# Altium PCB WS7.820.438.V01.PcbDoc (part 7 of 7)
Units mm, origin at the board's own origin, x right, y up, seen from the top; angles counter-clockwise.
Board outline 143.01 x 224 mm, 4 copper layers (Top Layer, G2, S3, Bottom Layer); 863 components, 638 nets, 2623 pads, 4664 vias.
Unrouted connection lines stored in the file: 16.
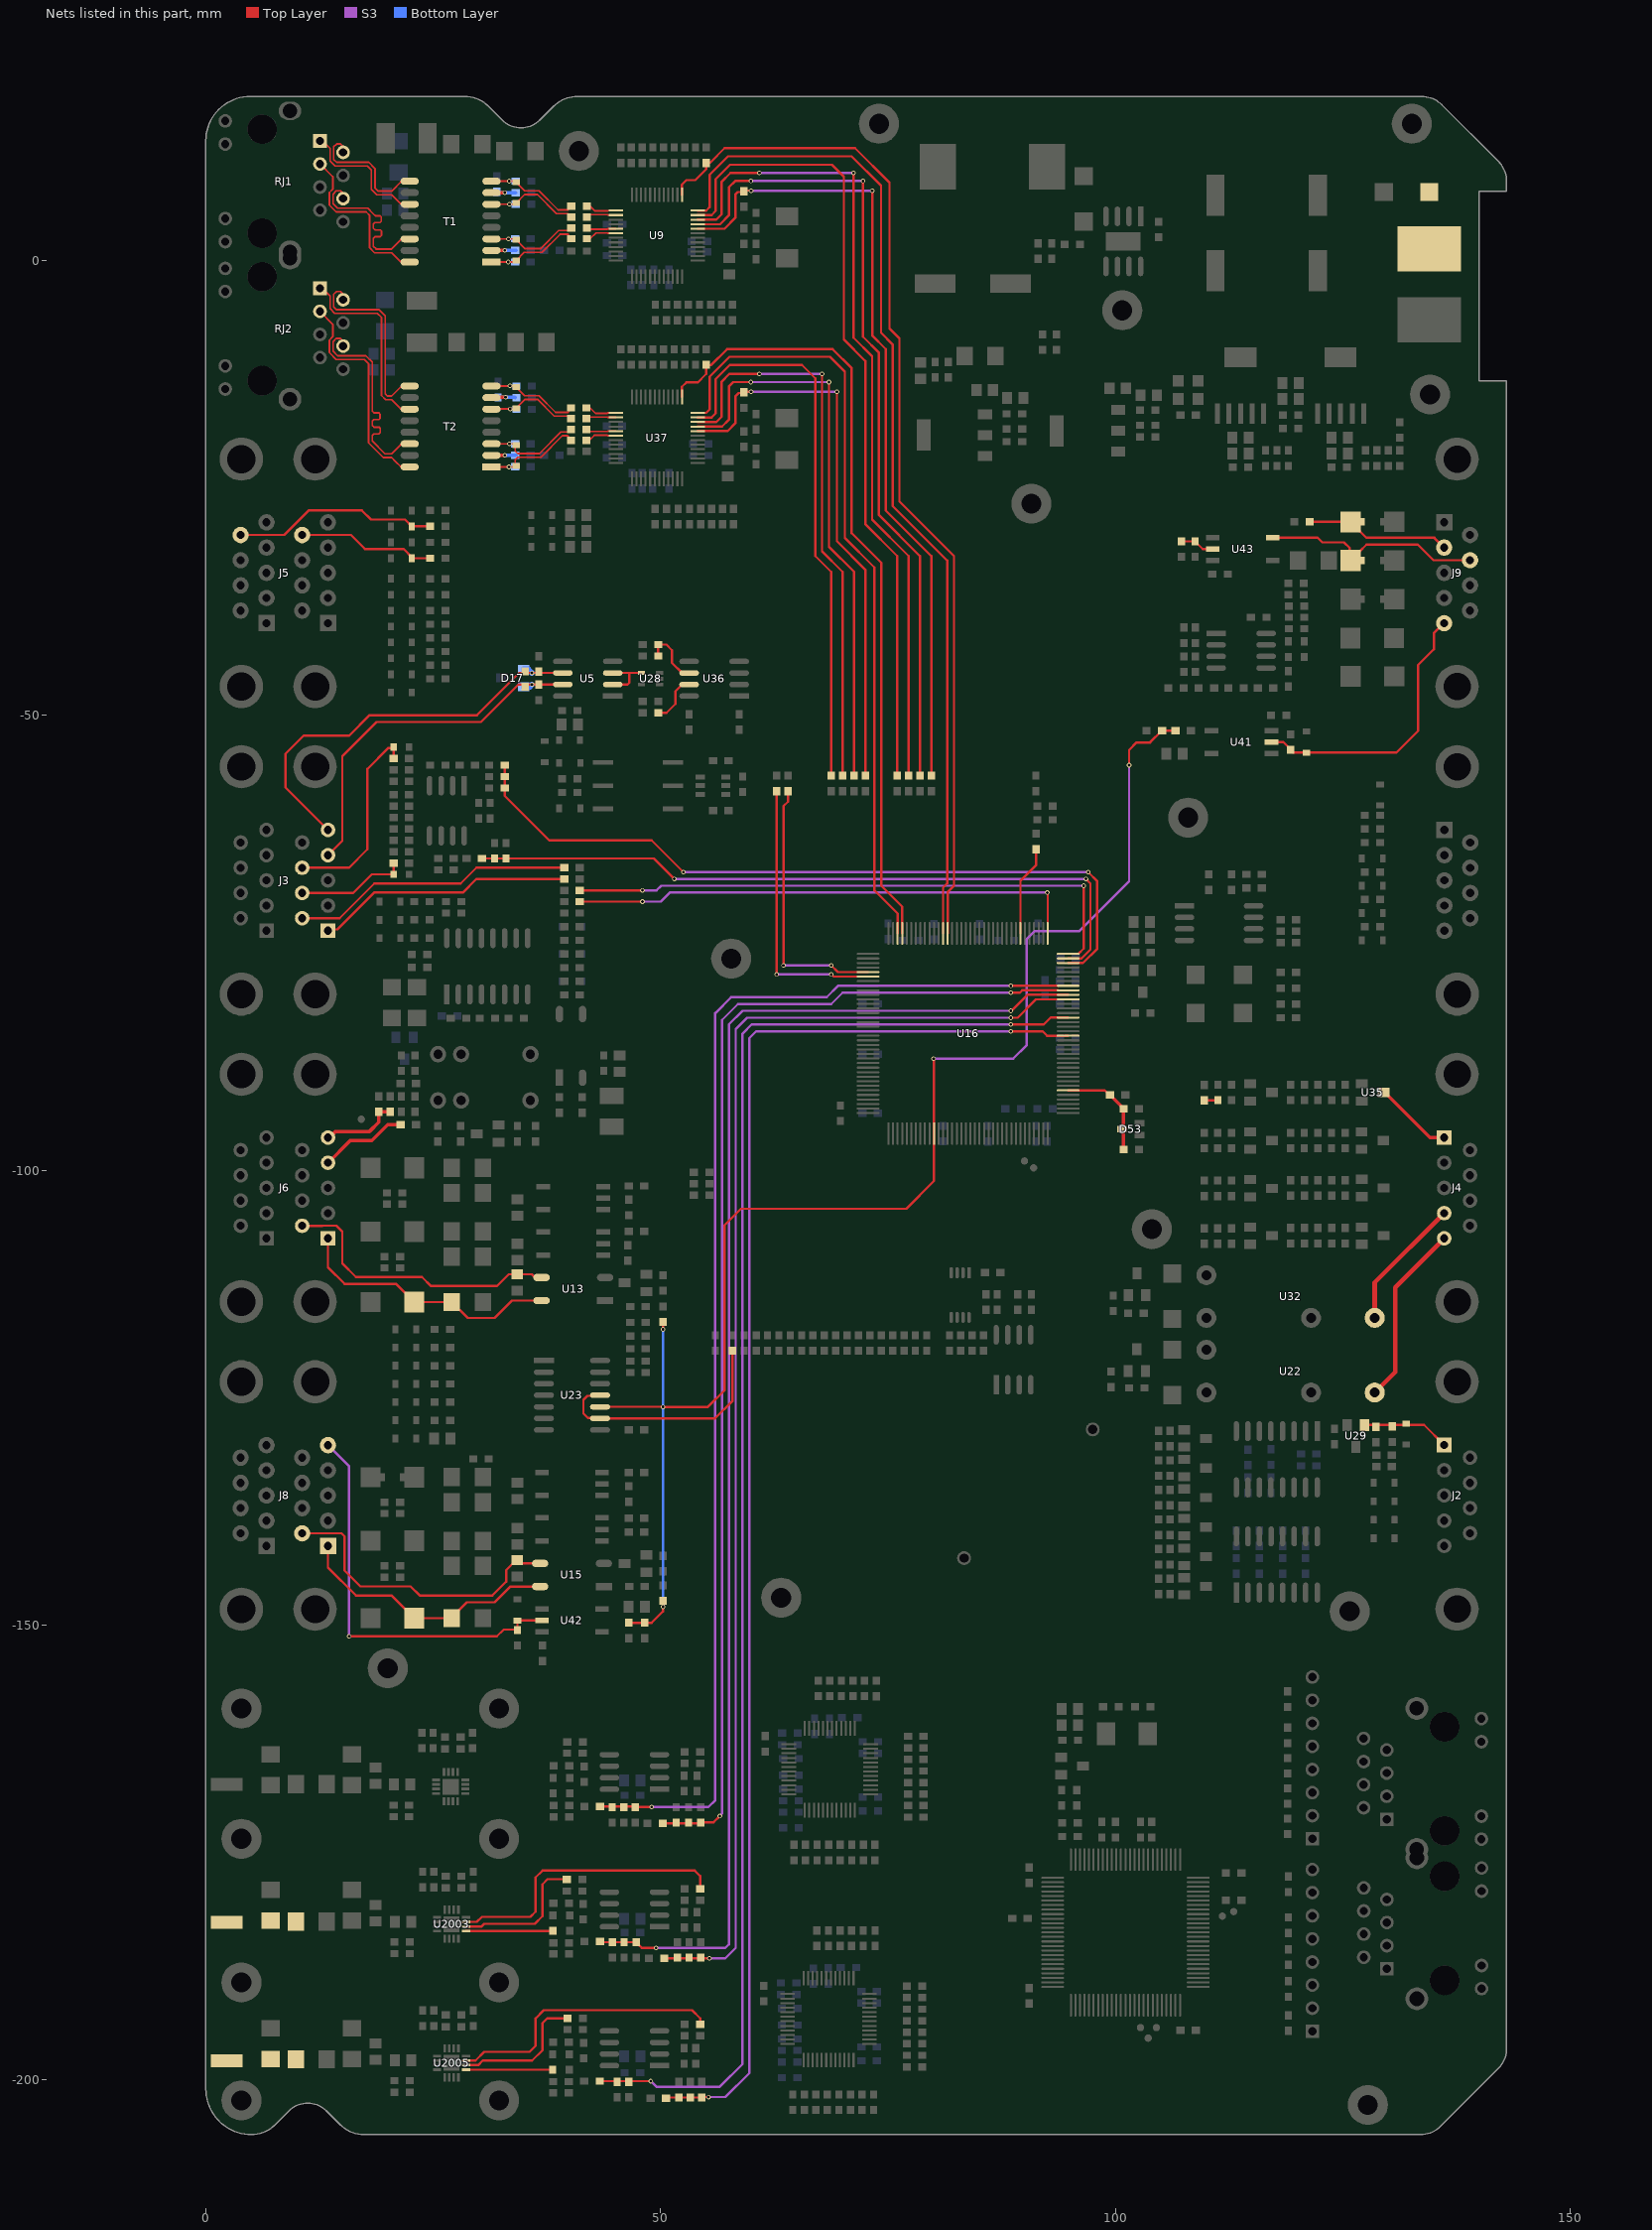
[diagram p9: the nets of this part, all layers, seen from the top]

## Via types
v1: diameter 0.508, hole 0.305, Top Layer to Bottom Layer, tented both sides, 4404 vias
v2: diameter 0.508, hole 0.3, Top Layer to Bottom Layer, tented both sides, 200 vias
v3: diameter 0.813, hole 0.508, Top Layer to Bottom Layer, tented both sides, 31 vias
v4: diameter 0.457, hole 0.305, Top Layer to Bottom Layer, tented both sides, 10 vias
v5: diameter 0.66, hole 0.406, Top Layer to Bottom Layer, tented both sides, 9 vias
v6: diameter 0.762, hole 0.406, Top Layer to Bottom Layer, tented both sides, 6 vias
v7: diameter 0.711, hole 0.406, Top Layer to Bottom Layer, tented both sides, 4 vias

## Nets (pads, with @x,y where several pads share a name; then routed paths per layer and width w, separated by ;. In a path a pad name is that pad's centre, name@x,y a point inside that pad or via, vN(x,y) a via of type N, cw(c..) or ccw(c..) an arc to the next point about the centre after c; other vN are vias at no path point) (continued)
PWM_Ext_IN: D65.1 D70.2 J9.7 U43.3 | length 24.9
  Top Layer w0.254: U43.3@117.3,-30.48 122.23,-30.48 122.75,-31 125.131,-31 125.749,-31.618 125.749,-32.899 D70.2@125.85,-33 ; D70.2@125.85,-32.95 126.823,-31.977 126.873,-31.977 127.6,-31.25 133.25,-31.25 134.966,-32.966 J9.7@138.979,-32.966
PWM_Ext_IN_ISO: R302.1 R317.2 U43.5 | length 3.9
  Top Layer w0.254: R302.1@107.25,-30.9 R317.2@108.75,-30.9 ; R317.2@108.692,-30.842 R317.2@108.75,-30.9 ; U43.5@110.7,-31.75 110.694,-31.744 109.594,-31.744 108.946,-31.096 108.896,-31.096 108.75,-30.95 R317.2@108.75,-30.9
PWM_Int: D34.2 D69.1 J9.2 R90.1 | length 16
  Top Layer w0.254: R90.1@121.35,-28.75 D34.2@125.85,-28.75 125.85,-28.8 126.823,-29.773 126.873,-29.773 127.6,-30.5 135.058,-30.5 J9.2@136.139,-31.581
RC2+_PSW: J6.B4 R224.1 | length 9.7
  Top Layer w0.381: J6.B4@13.426,-99.193 15.869,-96.75 18.25,-96.75 20,-95 R224.1@21.4,-95
RC2-_PSW: J6.B5 R313.1 R314.1 | length 8.5
  Top Layer w0.381: J6.B5@13.5,-96.25 13.759,-96.25 14.259,-95.75 18,-95.75 19,-94.75 R313.1@19,-93.6 R314.1@20.25,-93.6
red_24V: J4.1 U35.3 | length 8.7
  Top Layer w0.381: U35.3@129.47,-91.46 129.62,-91.46 134.583,-96.423 J4.1@136.139,-96.423
red_ctrl: R208.2 R299.1 | length 1.5
  Top Layer w0.254: R208.2@109.75,-92.35 111.23,-92.35 R299.1@111.27,-92.31
reset: C93.2 D27.1 J2.1 R153.1 U29.1 | length 9.7
  Top Layer w0.254: U29.1@127.376,-128.016 133.932,-128.016 J2.1@136.139,-130.223
RF_EN1: D54.1 J8.B5 R58.2 U42.5 | length 44.4
  Top Layer w0.254: v1(15.75,-151.25) 32,-151.25 32.75,-150.5 R58.2@34.25,-150.5 ; R58.2@34.25,-150.55 R58.2@34.25,-150.5 ; D54.1@34.25,-149.5 R58.2@34.25,-150.5 ; D54.1@34.35,-149.5 U42.5@36.95,-149.5
  S3 w0.254: J8.B5@13.426,-130.229 15.75,-132.553 v1(15.75,-151.25)
RF_EN2: D55.1 J9.5 R15.2 U41.5 | length 30.7
  Top Layer w0.254: U41.5@117.15,-52.96 118.45,-52.96 119.25,-53.76 R15.2@119.25,-53.81 119.25,-53.837 119.523,-54.11 D55.1@121,-54.11 130.89,-54.11 133.28,-51.72 133.28,-44.47 135,-42.75 135,-41 136.109,-39.891 J9.5@136.139,-39.891
RPD1: R2025.2 R2031.2 SMA2002.1
RPD2: R2043.2 R2049.2 SMA2003.1
RPD_EREF: R2028.1 U2003.9 | length 10.4
  Top Layer w0.254: U2003.9@28.607,-183.634 35.137,-183.634 ; 34.805,-183.621 37.146,-183.621 ; 36.592,-183.621 R2028.1@38.146,-183.621
RPD_EREF2: R2046.1 U2005.9 | length 9.5
  Top Layer w0.254: U2005.9@28.607,-198.874 37.043,-198.874 37.049,-198.881 R2046.1@38.121,-198.881
RPD_VENV: R2023.1 U2003.10 | length 15.3
  Top Layer w0.254: U2003.10@28.607,-183.134 30.324,-183.134 30.614,-182.844 36.156,-182.844 37,-182 37,-178.5 37.555,-177.945 39.667,-177.945 R2023.1@39.692,-177.97
RPD_VENV2: R2042.1 U2005.10 | length 15
  Top Layer w0.254: U2005.10@28.607,-198.374 29.943,-198.374 30.436,-197.881 35.869,-197.881 37,-196.75 37,-193.75 37.52,-193.23 39.692,-193.23 R2042.1@39.756,-193.23
RPD_VRMS: R2026.1 U2003.11 | length 31.9
  Top Layer w0.254: U2003.11@28.607,-182.634 29.797,-182.634 30.349,-182.082 35.668,-182.082 36.25,-181.5 36.25,-177.75 37,-177 53.75,-177 54.346,-177.596 R2026.1@54.346,-178.986
RPD_VRMS2: R2045.1 U2005.11 | length 30.8
  Top Layer w0.254: U2005.11@28.607,-197.874 29.636,-197.874 30.594,-196.916 35.584,-196.916 36.25,-196.25 36.25,-193.25 37.159,-192.341 53.455,-192.341 54.344,-193.23 R2045.1@54.344,-193.907
RS485-A_POWER: D17.1 J3.B5 R44.2 R186.2 U5.6 | length 45.5
  Top Layer w0.254: J3.B5@13.426,-62.617 8.75,-57.941 8.75,-54.25 10.75,-52.25 15.75,-52.25 18,-50 29.809,-50 34.45,-45.359 35.082,-45.359 v1(35.845,-45.359) U5.6@39.234,-45.359
  Bottom Layer w0.635: D17.1@34.937,-44.962 35.448,-44.962 v1(35.845,-45.359)
RS485-B_POWER: D17.2 J3.B4 R33.1 R186.1 U5.7 | length 39.7
  Top Layer w0.254: J3.B4@13.426,-65.387 15,-63.813 15,-54.5 18.75,-50.75 30.25,-50.75 34.371,-46.629 34.83,-46.629 R186.1@35.082,-46.882 ; 35.484,-46.629 v1(35.845,-46.629) U5.7@39.234,-46.629
  Bottom Layer w0.635: D17.2@34.937,-46.862 35.613,-46.862 v1(35.845,-46.629)
RTC: R61.2 T1.2 | length 2.7
  Top Layer w0.381: T1.2@31.404,1.073 31.416,1.085 v1(32.855,1.085)
  Bottom Layer w0.381: v1(32.855,1.085) 32.867,1.073 R61.2@34.106,1.073
RTC2: R263.2 T2.2 | length 2.7
  Top Layer w0.381: T2.2@31.404,-21.445 31.416,-21.433 v1(32.855,-21.433)
  Bottom Layer w0.381: v1(32.855,-21.433) 32.867,-21.445 R263.2@34.106,-21.445
RX1_N: RJ1.6 T1.14 | length 18.8
  Top Layer w0.191: RJ1.6@15.09,6.787 15.09,7.357 14.821,7.626 14.339,7.626 13.983,7.27 13.983,6.229 14.491,5.721 17.791,5.721 18.415,5.097 18.618,4.894 19.152,4.894 19.279,4.767 19.279,4.284 19.152,4.157 18.593,4.157 18.415,3.979 18.415,3.522 18.618,3.319 19.177,3.319 19.304,3.192 19.304,2.735 19.152,2.582 18.593,2.582 18.415,2.404 18.415,1.541 18.72,1.236 20.42,1.236 21.515,2.331 22.416,2.331 T1.14@22.404,2.343
RX1_P: RJ1.3 T1.16 | length 18.8
  Top Layer w0.191: RJ1.3@12.55,10.597 12.555,10.592 13.958,9.189 13.958,7.82 13.577,7.439 13.577,6.061 14.323,5.315 17.623,5.315 18.009,4.928 18.009,1.372 18.551,0.83 20.42,0.83 21.459,-0.209 T1.16@22.416,-0.209
RX2_N: R272.1 U37.5 | length 3.4
  Top Layer w0.191: R272.1@41.831,-18.606 42.048,-18.822 44.144,-18.822 44.191,-18.775 U37.5@45.092,-18.775
RX2_P: R270.1 U37.6 | length 3.5
  Top Layer w0.191: R270.1@41.831,-19.797 42.15,-19.797 42.718,-19.229 44.144,-19.229 44.191,-19.275 U37.6@45.092,-19.275
RX12_N: RJ2.6 T2.14 | length 26.6
  Top Layer w0.191: RJ2.6@15.09,-9.432 15.09,-8.862 14.821,-8.593 14.339,-8.593 13.983,-8.948 13.983,-9.99 14.492,-10.499 17.593,-10.499 18.288,-11.194 18.288,-16.468 ; 18.288,-14.282 18.288,-16.568 18.491,-16.771 19.025,-16.771 19.152,-16.898 19.152,-17.381 19.025,-17.508 18.466,-17.508 18.288,-17.686 18.288,-18.143 18.491,-18.346 19.05,-18.346 19.177,-18.473 19.177,-18.93 19.025,-19.083 18.466,-19.083 18.288,-19.26 18.288,-19.871 19.687,-21.27 20.408,-21.27 21.503,-20.175 T2.14@22.404,-20.175 T2.14@22.392,-20.163
RX12_P: RJ2.3 T2.16 | length 26.7
  Top Layer w0.191: RJ2.3@12.55,-5.622 13.958,-7.03 13.958,-8.399 13.577,-8.78 13.577,-10.158 14.324,-10.905 17.424,-10.905 17.882,-11.362 17.882,-16.468 ; 17.882,-14.114 17.882,-20.04 19.518,-21.677 20.408,-21.677 20.884,-22.152 21.447,-22.715 T2.16@22.404,-22.715
RX_N: R70.1 U9.5 | length 3.3
  Top Layer w0.191: R70.1@41.877,3.562 42.022,3.416 44.144,3.416 44.191,3.463 U9.5@45.092,3.463
RX_P: R68.1 U9.6 | length 3.5
  Top Layer w0.191: R68.1@41.877,2.368 42.237,2.368 42.879,3.01 44.144,3.01 44.191,2.963 U9.6@45.092,2.963
SPI1_MISO: R328.1 U37.34 | length 62.7
  Top Layer w0.254: U37.34@54.092,-17.775 56.113,-17.775 56.711,-17.177 56.711,-13.332 57.547,-12.497 v1(60.858,-12.497) ; v1(67.739,-12.497) 67.739,-32 70,-34.261 70,-56.195
  S3 w0.254: v1(60.858,-12.497) v1(67.739,-12.497)
SPI1_MOSI: R329.1 U37.35 | length 62.5
  Top Layer w0.254: U37.35@54.092,-17.275 55.597,-17.275 56.051,-16.821 56.051,-13.058 57.603,-11.506 65.532,-11.506 67,-12.974 67,-32.5 68.75,-34.25 R329.1@68.75,-56.65
SPI1_NSS: R271.1 R327.1 U37.32 | length 62.3
  Top Layer w0.254: U37.32@54.092,-18.775 57.348,-18.775 58.21,-17.913 58.21,-14.979 58.592,-14.597 59.063,-14.597 R271.1@59.142,-14.517 ; R271.1@59.216,-14.444 59.935,-14.444 v1(59.944,-14.453) ; v1(69.373,-14.453) 69.373,-30.873 72.5,-34 R327.1@72.5,-56.788
  S3 w0.254: v1(59.944,-14.453) v1(69.373,-14.453)
SPI1_SCK: R326.1 U37.33 | length 62.8
  Top Layer w0.254: U37.33@54.092,-18.275 56.756,-18.275 57.499,-17.532 57.499,-13.868 57.981,-13.386 v1(59.919,-13.386) ; v1(68.504,-13.386) 68.504,-13.556 68.511,-13.564 68.511,-31.5 71.25,-34.239 R326.1@71.25,-56.481
  S3 w0.254: v1(59.919,-13.386) v1(68.504,-13.386)
SPI2_MISO: R30.2 U9.34 | length 90.1
  Top Layer w0.254: U9.34@54.092,4.463 56.113,4.463 56.711,5.062 56.711,8.639 57.674,9.601 v1(60.858,9.601) ; v1(71.202,9.601) 71.202,-8.503 73.25,-10.551 73.25,-28.5 77.25,-32.5 R30.2@77.25,-56.656
  S3 w0.254: v1(60.858,9.601) v1(71.202,9.601)
SPI2_MOSI: R29.2 U9.35 | length 89.4
  Top Layer w0.254: U9.35@54.092,4.963 55.597,4.963 56.051,5.417 56.051,8.913 57.629,10.49 68.834,10.49 70.135,9.189 70.135,-8.706 72.5,-11.071 72.5,-29 76,-32.5 R29.2@76,-56.833
SPI2_NSS: R35.2 R69.1 U9.32 | length 89.5
  Top Layer w0.254: U9.32@54.092,3.463 57.018,3.463 58.21,4.655 58.21,7.232 58.479,7.501 59.063,7.501 R69.1@59.142,7.581 ; R69.1@59.216,7.654 59.935,7.654 v1(59.944,7.645) ; v1(73.259,7.645) 73.259,-8.274 74.75,-9.765 74.75,-27.5 79.75,-32.5 R35.2@79.75,-56.833
  S3 w0.254: v1(59.944,7.645) v1(73.259,7.645)
SPI2_SCK: R32.2 U9.33 | length 90
  Top Layer w0.254: U9.33@54.092,3.963 56.527,3.963 57.499,4.935 57.499,8.02 58.191,8.712 v1(59.919,8.712) ; v1(72.243,8.712) 72.243,-8.401 74,-10.158 74,-28 78.5,-32.5 R32.2@78.5,-56.796
  S3 w0.254: v1(59.919,8.712) v1(72.243,8.712)
State_out1+: D48.2 J6.B1 R189.1 U13.6 | length 29.8
  Top Layer w0.254: J6.B1@13.426,-107.503 13.426,-110.676 15.25,-112.5 20.9,-112.5 21.877,-113.477 21.927,-113.477 22.9,-114.45 D48.2@22.9,-114.5 R189.1@27.05,-114.5 27.05,-114.6 27.823,-115.373 27.923,-115.373 28.8,-116.25 31.75,-116.25 33.655,-114.345 U13.6@36.9,-114.345
State_out1-: FB21.1 J6.B6 U13.4 | length 31.7
  Top Layer w0.254: J6.B6@10.586,-106.118 12.775,-106.118 12.788,-106.105 14.355,-106.105 15,-106.75 15,-110.25 16.5,-111.75 23.75,-111.75 24.75,-112.75 32,-112.75 33.295,-111.455 FB21.1@34.225,-111.455 34.227,-111.457 35.828,-111.457 36.176,-111.805 U13.4@36.75,-111.805
State_out2+: D50.2 J8.B1 R193.1 U15.6 | length 29.4
  Top Layer w0.254: J8.B1@13.426,-141.309 13.426,-143.676 16.5,-146.75 20.4,-146.75 D50.2@22.9,-149.25 R193.1@27.05,-149.25 27.05,-149.15 27.823,-148.377 28.7,-147.5 ; 28.75,-147.5 31.75,-147.5 33.48,-145.77 U15.6@36.75,-145.77
State_out2-: FB23.1 J8.B6 U15.4 | length 33.7
  Top Layer w0.254: J8.B6@10.586,-139.924 14.924,-139.924 15.25,-140.25 15.25,-144 17,-145.75 22.5,-145.75 23.5,-146.75 31.5,-146.75 33.025,-145.225 33.025,-143.95 34.125,-142.85 FB23.1@34.225,-142.85 34.605,-143.23 U15.4@36.75,-143.23
SW1_24V: J4.5 U22.3 | length 20.1
  Top Layer w0.508: U22.3@128.5,-124.45 130.75,-122.2 130.75,-112.891 J4.5@136.139,-107.503
SW2_24V: J4.4 U32.3 | length 14.7
  Top Layer w0.508: U32.3@128.5,-116.25 128.5,-112.371 J4.4@136.139,-104.733
T_DE3: U5.2 U5.3 U28.4 | length 6.1
  Top Layer w0.254: U5.2@44.734,-46.629 46.348,-46.629 46.564,-46.414 46.564,-45.359 ; U5.3@44.734,-45.359 46.564,-45.359 ; U28.4@47.882,-45.35 47.873,-45.359 46.564,-45.359
TCT: C41.2 R66.1 T1.7 | length 3.7
  Top Layer w0.381: T1.7@31.416,7.435 v1(32.868,7.435)
  Bottom Layer w0.381: C41.2@31.877,7.405 31.907,7.435 v1(32.868,7.435) 34.063,7.435 R66.1@34.075,7.423
TCT2: C235.2 R268.1 T2.7 | length 3.5
  Top Layer w0.381: T2.7@31.508,-15.062 v1(32.959,-15.062)
  Bottom Layer w0.381: C235.2@31.969,-15.092 31.998,-15.062 v1(32.959,-15.062) 33.977,-15.062 R268.1@34.018,-15.103
TEMP11_LED: D3.1 J5.A9 R23.1 | length 22.7
  Top Layer w0.254: J5.A9@3.826,-30.196 8.604,-30.196 11.3,-27.5 17.166,-27.5 18.166,-28.5 21.9,-28.5 D3.1@22.65,-29.25 R23.1@24.65,-29.25
TEMP22_LED: D8.1 J5.B9 R169.1 | length 15.1
  Top Layer w0.254: J5.B9@10.586,-30.196 15.946,-30.196 17.5,-31.75 21.75,-31.75 22.75,-32.75 R169.1@24.65,-32.75
TX1_N: RJ1.2 T1.9 | length 14.8
  Top Layer w0.191: RJ1.2@15.09,11.867 15.09,12.513 14.821,12.782 14.364,12.782 14.059,12.477 14.059,11.08 14.364,10.776 17.915,10.776 18.593,10.097 18.593,7.965 18.96,7.598 20.408,7.598 21.503,8.693 T1.9@22.404,8.693 T1.9@22.392,8.705
TX1_P: RJ1.1 T1.11 | length 14.8
  Top Layer w0.191: RJ1.1@12.55,13.137 12.816,13.137 13.653,12.3 13.653,10.912 14.196,10.369 17.746,10.369 18.186,9.929 18.186,7.797 18.792,7.191 20.408,7.191 21.447,6.153 T1.11@22.404,6.153
TX2_N: R274.1 U37.1 | length 3.5
  Top Layer w0.191: R274.1@41.831,-16.223 42.253,-16.223 42.852,-16.822 44.144,-16.822 44.191,-16.775 U37.1@45.092,-16.775
TX2_P: R273.1 U37.2 | length 3.4
  Top Layer w0.191: R273.1@41.831,-17.415 42.017,-17.229 44.144,-17.229 44.191,-17.275 U37.2@45.092,-17.275
TX12_N: RJ2.2 T2.9 | length 21.2
  Top Layer w0.191: RJ2.2@15.09,-4.352 15.09,-3.705 14.821,-3.437 14.364,-3.437 14.059,-3.741 14.059,-5.138 14.339,-5.418 19.025,-5.418 19.71,-6.104 19.71,-14.69 19.941,-14.92 20.408,-14.92 21.503,-13.825 T2.9@22.404,-13.825 T2.9@22.392,-13.813
TX12_P: RJ2.1 T2.11 | length 21.2
  Top Layer w0.191: RJ2.1@12.55,-3.082 12.816,-3.082 13.653,-3.919 13.653,-5.307 14.17,-5.824 18.856,-5.824 19.304,-6.272 19.304,-14.858 19.772,-15.327 20.408,-15.327 21.447,-16.365 T2.11@22.404,-16.365
TX_N: R72.1 U9.1 | length 3.5
  Top Layer w0.191: R72.1@41.877,5.95 42.255,5.95 42.788,5.416 44.144,5.416 44.191,5.463 U9.1@45.092,5.463
TX_P: R71.1 U9.2 | length 3.3
  Top Layer w0.191: R71.1@41.877,4.756 42.131,5.01 44.144,5.01 44.191,4.963 U9.2@45.092,4.963
UART1_RX: J3.B1 R177.1 | length 28.3
  Top Layer w0.254: J3.B1@13.426,-73.697 13.581,-73.542 14.458,-73.542 18.5,-69.5 28.25,-69.5 29.75,-68 R177.1@39.4,-68
UART1_TX: J3.B6 R178.1 | length 31.1
  Top Layer w0.254: J3.B6@10.586,-72.312 14.71,-72.312 18.521,-68.5 28,-68.5 29.75,-66.75 R178.1@39.4,-66.75
UART2_RX: R13.1 U16.37 | length 56.3
  Top Layer w0.254: R13.1@41.134,-70.5 v1(48,-70.5) ; v1(92.5,-69.5) 92.5,-69.569 92.551,-69.619 U16.37@92.551,-73.987
  S3 w0.254: v1(48,-70.5) 50,-70.5 51,-69.5 v1(92.5,-69.5)
UART2_TX: R14.1 U16.36 | length 63.3
  Top Layer w0.254: R14.1@41.093,-69.25 v1(48,-69.25) ; U16.36@95.924,-76.22 96.5,-75.644 v1(96.5,-68.75)
  S3 w0.254: v1(48,-69.25) 49.558,-69.25 50.058,-68.75 v1(96.5,-68.75)
UART3_RX: R211.1 U16.78 | length 30.3
  Top Layer w0.254: v1@62.75,-78.535 v1(62.75,-78.5) R211.1@62.75,-58.35 ; v1(68.75,-78.5) 68.788,-78.5 69.026,-78.737 U16.78@72.801,-78.737
  S3 w0.254: v1(62.75,-78.5) v1(68.75,-78.5)
UART3_RX-2: R36.1 U36.7 | length 5.5
  Top Layer w0.254: R36.1@49.732,-49.75 50.632,-49.75 51.632,-48.75 51.632,-47.36 52.357,-46.635 U36.7@53.132,-46.635
UART3_TX: R212.1 U16.77 | length 29
  Top Layer w0.254: v1(63.5,-77.5) 63.5,-60 64,-59.5 R212.1@64,-58.35 ; v1(68.75,-77.5) 69.487,-78.237 U16.77@72.801,-78.237
  S3 w0.254: v1(63.5,-77.5) v1(68.75,-77.5)
UART3_TX-2: R41.1 R210.1 U36.6 | length 6.8
  Top Layer w0.254: R210.1@49.732,-43.5 R41.1@49.732,-42.25 50.632,-42.25 51.25,-42.868 51.25,-44.258 52.357,-45.365 U36.6@53.132,-45.365
USERLOCK: R222.2 U23.9 U23.11 | length 26.6
  Top Layer w0.254: U23.11@43.336,-124.75 43.27,-124.816 41.934,-124.816 41.5,-125.25 41.5,-126.75 41.992,-127.242 43.288,-127.242 U23.9@43.336,-127.29 55.971,-127.29 57.912,-125.349 R222.2@57.912,-119.775
USERLOCK_EN: R16.1 R105.1 R190.1 R197.1 R323.2 R324.2 U16.119 U23.10 | length 164.1
  Top Layer w0.254: U23.10@43.836,-126.02 43.839,-126.023 50.247,-126.023 v2(50.25,-126.026) 55.203,-126.026 57.023,-124.206 57.023,-106.045 58.818,-104.25 77,-104.25 80.051,-101.199 U16.119@80.051,-95.987 80.034,-95.97 80.034,-87.784 v1(80,-87.75) ; R105.1@46.5,-149.75 49,-149.75 50.25,-148.5 R197.1@50.25,-147.35 ; v1(50.25,-117.5) R190.1@50.25,-116.75 ; v1(101.5,-55.5) 101.5,-53.821 102.321,-53 103.806,-53 R323.2@105.117,-51.689 R16.1@106.592,-51.689
  S3 w0.254: v1(80,-87.75) 88.75,-87.75 90.25,-86.25 90.25,-74.586 91.086,-73.75 96,-73.75 101.5,-68.25 v1(101.5,-55.5)
  Bottom Layer w0.254: v1(50.25,-148) v2(50.25,-126.026) v1(50.25,-117.5)
Vbat: C18.2 C55.2 D53.3 R216.2 U16.6 | length 11.4
  Top Layer w0.254: U16.6@94.801,-91.237 98.837,-91.237 C55.2@99.35,-91.75
  Top Layer w0.381: C55.2@99.35,-91.75 C55.2@99.4,-91.75 99.45,-91.75 99.66,-91.96 99.66,-92.009 100.64,-92.99 100.64,-93.04 100.85,-93.25 C18.2@100.9,-93.25 D53.3@100.9,-95.35 ; D53.3@100.75,-95.5 100.9,-95.65 R216.2@100.9,-97.75
VENV2-: C2037.2 C2038.2 R2044.1 U16.22 | length 166.8
  Top Layer w0.254: R2044.1@43.302,-200.13 v1(48.916,-200.13) ; v1(88.5,-84) 92.125,-84 92.888,-83.237 U16.22@94.801,-83.237
  S3 w0.254: v1(48.916,-200.13) 49.536,-200.75 56.5,-200.75 59,-198.25 59,-85 60,-84 v1(88.5,-84)
VENV+: C2012.2 C2014.2 R2007.1 R2058.1 U16.29 | length 138.4
  Top Layer w0.254: R2007.1@43.328,-169.955 47.199,-169.955 47.244,-170 v1(49,-170) ; v1(88.5,-79.75) 89.5,-79.75 89.513,-79.737 U16.29@93.678,-79.737
  S3 w0.254: v1(49,-170) 55.25,-170 56,-169.25 56,-82.75 57.75,-81 68.25,-81 69.5,-79.75 v1(88.5,-79.75)
VENV-: C2023.2 C2024.2 R2024.1 R2059.1 U16.27 | length 154.4
  Top Layer w0.254: R2024.1@43.328,-184.794 43.401,-184.867 R2059.1@47.299,-184.867 47.299,-184.917 47.572,-185.19 47.622,-185.19 47.932,-185.5 v1(49.5,-185.5) ; v1(88.5,-82.5) 88.569,-82.5 90.331,-80.737 U16.27@94.801,-80.737
  S3 w0.254: v1(49.5,-185.5) 57.101,-185.5 57.5,-185.101 57.5,-84 59,-82.5 v1(88.5,-82.5)
VIN: D64.1 J7.1
VOLT_DEC: R180.1 U16.43 | length 10
  Top Layer w0.254: U16.43@89.551,-73.987 89.551,-68.199 91.288,-66.462 R180.1@91.288,-64.734
VRMS2-: C2041.2 C2042.2 R2040.2 R2048.2 U16.18 | length 159.6
  Top Layer w0.254: R2040.2@50.6,-202 50.673,-201.927 R2048.2@52,-201.927 C2041.2@54.5,-201.927 ; C2041.2@54.5,-201.889 v1(55.262,-201.889) ; v1(88.5,-84.75) 92,-84.75 92.487,-85.237 U16.18@94.801,-85.237
  S3 w0.254: v1(55.262,-201.889) 57.111,-201.889 59.75,-199.25 59.75,-85.5 60.5,-84.75 v1(88.5,-84.75)
VRMS+: C2011.2 C2013.2 R2001.2 R2008.2 U16.28 | length 132.5
  Top Layer w0.254: R2001.2@50.24,-171.801 51.698,-171.801 53.077,-171.801 54.42,-171.801 C2013.2@54.42,-171.728 54.47,-171.678 55.822,-171.678 v1(56.5,-171) ; v1(88.5,-80.5) 89.5,-80.5 89.763,-80.237 U16.28@93.678,-80.237
  S3 w0.254: v1(56.5,-171) 56.5,-170.974 56.75,-170.724 56.75,-83.5 58.5,-81.75 68.75,-81.75 70,-80.5 v1(88.5,-80.5)
VRMS-: C2027.2 C2028.2 R2022.2 R2030.2 U16.26 | length 147.2
  Top Layer w0.254: R2022.2@50.409,-186.64 v1(55.367,-186.64) ; v1(88.5,-83.25) 89.25,-83.25 91.263,-81.237 U16.26@94.801,-81.237
  S3 w0.254: v1(55.367,-186.64) 57.11,-186.64 58.25,-185.5 58.25,-84.5 59.5,-83.25 v1(88.5,-83.25)
W5500_INTN: U9.36 U16.60 | length 111.4
  Top Layer w0.254: U9.36@54.092,5.463 55.005,5.463 55.391,5.849 55.391,9.405 57.415,11.43 70.993,11.43 74.224,8.199 74.224,-7.969 75.5,-9.245 75.5,-27 81.5,-33 81.5,-68.5 81.051,-68.949 U16.60@81.051,-73.987
W5500_INTN1: U16.70 U37.36 | length 85.6
  Top Layer w0.254: U37.36@54.092,-16.775 55.005,-16.775 55.391,-16.389 55.391,-12.785 57.558,-10.617 68.617,-10.617 70.25,-12.25 70.25,-30.5 73.5,-33.75 73.5,-69.25 76.051,-71.801 U16.70@76.051,-73.987
W5500_RSTN: R67.1 U9.37 U16.59 | length 113.3
  Top Layer w0.254: U9.37@52.342,7.213 52.342,8.326 52.825,8.809 53.804,8.809 55.01,10.015 55.01,10.753 55.469,10.753 57.034,12.319 71.374,12.319 75.164,8.529 75.164,-7.512 76.25,-8.598 76.25,-26.5 82.25,-32.5 82.25,-68.75 81.551,-69.449 U16.59@81.551,-73.987
W5500_RSTN1: R269.1 U16.69 U37.37 | length 87.4
  Top Layer w0.254: U37.37@52.342,-15.025 52.342,-13.913 52.825,-13.429 54.07,-13.429 55.01,-12.49 R269.1@55.01,-11.536 ; R269.1@55.01,-11.485 R269.1@55.01,-11.536 ; U16.69@76.551,-73.987 76.551,-71.051 74.25,-68.75 74.25,-33.25 71,-30 71,-11.857 68.897,-9.754 57.314,-9.754 55.531,-11.536 R269.1@55.01,-11.536
W5500_RX1_N: D23.2 R63.2 R70.2 T1.3 | length 10.9
  Top Layer w0.191: T1.3@31.404,2.343 v1(33.274,2.343) 34.004,2.343 D23.2@34.004,2.26 ; D23.2@34.106,2.26 35.096,1.27 36.784,1.27 38.784,3.27 39.808,3.27 R70.2@40.177,3.638
  Bottom Layer w0.191: v1(33.274,2.343) 33.967,2.343 R63.2@34.004,2.381
W5500_RX1_P: D23.1 R65.2 R68.2 T1.1 | length 11.1
  Top Layer w0.191: T1.1@31.404,-0.197 v1(33.249,-0.197) 33.949,-0.197 D23.1@34.004,-0.142 ; D23.1@34.004,-0.197 D23.1@34.004,-0.142 ; D23.1@34.004,-0.04 D23.1@34.004,-0.142 ; R68.2@40.177,2.495 39.808,2.863 38.952,2.863 36.953,0.864 35.01,0.864 D23.1@34.106,-0.04 D23.1@34.004,-0.142
  Bottom Layer w0.191: v1(33.249,-0.197) R65.2@34.004,-0.197
W5500_RX2_N: D25.2 R265.2 R272.2 T2.3 | length 11.6
  Top Layer w0.191: T2.3@31.404,-20.175 v1(33.376,-20.175) 33.986,-20.175 D25.2@34.106,-20.295 ; D25.2@34.004,-20.295 34.004,-20.974 34.278,-21.248 36.66,-21.248 39.027,-18.88 39.863,-18.88 R272.2@40.177,-18.567
  Bottom Layer w0.191: v1(33.376,-20.175) R265.2@34.145,-20.175
W5500_RX2_P: D25.1 R267.2 R270.2 T2.1 | length 11.7
  Top Layer w0.191: T2.1@31.404,-22.715 v1(33.325,-22.715) 33.986,-22.715 D25.1@34.106,-22.595 ; D25.1@34.004,-22.595 34.004,-21.91 34.26,-21.654 36.828,-21.654 39.196,-19.286 39.796,-19.286 R270.2@40.177,-19.667
  Bottom Layer w0.191: v1(33.325,-22.715) 34.125,-22.715 R267.2@34.145,-22.695
W5500_TX1_N: D24.1 R62.1 R72.2 T1.8 | length 11
  Top Layer w0.191: T1.8@31.404,8.693 v1(33.35,8.693) 33.986,8.693 34.106,8.573 35.041,7.638 36.615,7.638 38.723,5.53 39.808,5.53 R72.2@40.177,5.899
  Bottom Layer w0.191: v1(33.35,8.693) R62.1@34.075,8.693
W5500_TX1_P: D24.2 R64.1 R71.2 T1.6 | length 10.9
  Top Layer w0.191: T1.6@31.404,6.153 v1(33.376,6.153) 33.986,6.153 34.106,6.273 35.065,7.231 36.447,7.231 38.554,5.124 39.808,5.124 R71.2@40.177,4.756
  Bottom Layer w0.191: v1(33.376,6.153) R64.1@34.075,6.153
W5500_TX2_N: D26.1 R264.1 R274.2 T2.8 | length 13
  Top Layer w0.191: T2.8@31.404,-13.825 33.971,-13.825 D26.1@34.106,-13.96 35.026,-14.88 36.615,-14.88 38.456,-16.721 39.821,-16.721 R274.2@40.177,-16.365 ; T2.8@31.496,-13.804 v1(33.442,-13.804) ; D26.1@34.078,-13.804 D26.1@34.198,-13.924
  Bottom Layer w0.191: v1(33.442,-13.804) R264.1@34.124,-13.804 ; R264.1@34.145,-13.825 R264.1@34.124,-13.804 ; R264.1@34.167,-13.804 R264.1@34.124,-13.804
W5500_TX2_P: D26.2 R266.1 R273.2 T2.6 | length 13
  Top Layer w0.191: T2.6@31.404,-16.365 34.001,-16.365 D26.2@34.106,-16.26 35.079,-15.287 36.447,-15.287 38.288,-17.127 39.838,-17.127 R273.2@40.177,-17.466 ; T2.6@31.496,-16.344 v1(33.467,-16.344) ; D26.2@34.078,-16.344 D26.2@34.198,-16.224
  Bottom Layer w0.191: v1(33.467,-16.344) 34.145,-16.344 R266.1@34.167,-16.344
waterflow1: D15.2 FB35.1 J3.B7 | length 12.2
  Top Layer w0.254: J3.B7@10.586,-69.542 16.208,-69.542 18.25,-67.5 D15.2@20.65,-67.5 FB35.1@20.65,-66.25
waterflow_CPU1: C126.2 C127.2 R318.2 U16.35 | length 78.1
  Top Layer w0.254: R318.2@30.35,-65.75 C126.2@31.75,-65.75 C127.2@33,-65.75 49.25,-65.75 v1(51.5,-68) ; U16.35@94.801,-76.737 96.263,-76.737 97.25,-75.75 97.25,-68.5 v1(96.75,-68)
  S3 w0.254: v1(51.5,-68) v1(96.75,-68)
watertemp1: D14.2 FB34.1 J3.B8 | length 22
  Top Layer w0.254: J3.B8@10.586,-66.772 15.728,-66.772 17.75,-64.75 17.75,-55.916 20.068,-53.598 20.552,-53.598 D14.2@20.65,-53.5 FB34.1@20.65,-54.75
watertemp_CPU1: C85.2 C122.2 R151.2 U16.34 | length 83.7
  Top Layer w0.254: R151.2@32.85,-55.5 C122.2@32.85,-56.75 C85.2@32.85,-58 32.85,-58.85 37.75,-63.75 49,-63.75 v1(52.5,-67.25) ; U16.34@94.801,-77.237 96.432,-77.237 98,-75.669 98,-68.25 v1(97,-67.25)
  S3 w0.254: v1(52.5,-67.25) v1(97,-67.25)
pads on no net: J8.B4 J10.9 J10.10 J10.11 J10.12 J10.15 J10.16 RJ1.15 RJ1.16 RJ2.15 RJ2.16 RJ3.9 RJ3.10 RJ3.11 RJ3.12 RJ3.15 RJ3.16 T1.4 T1.5 T1.12 T1.13 T2.4 T2.5 T2.12 T2.13 U2.23 U2.24 U2.35 U2.36 U2.70 U2.71 U2.73 U2.91 U2.95 U2.96 U3.7 U3.9 U9.7 U9.12 U9.13 U9.18 U9.24 U9.26 U9.46 U9.47 U10.3 U16.24 U17.3 U19.2 U19.3 U19.5 U19.6 U19.7 U20.4 U27.4 U28.1 U37.7 U37.12 U37.13 U37.18 U37.24 U37.26 U37.46 U37.47 U40.3 U40.4 U40.13 U40.14 U2001.6 U2001.7 U2001.8 U2001.12 U2001.13 U2003.6 U2003.7 U2003.8 U2003.12 U2003.13 U2005.6 U2005.7 U2005.8 U2005.12 U2005.13 X3.1

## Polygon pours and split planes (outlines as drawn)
GND on Bottom Layer "Top Layer-No Net" (solid, remove dead copper, pour order 1018): -3.785,19.523 144.08,19.523 144.08,-206 -3.683,-206 -3.683,-150.86 -3.683,19.396
GND2 on Bottom Layer "GND2_L04_P1010" (solid, remove dead copper, pour order 1010): 55.5,-52.75 55.5,-41.75 33.75,-41.75 27,-48.5 11.75,-48.5 7.25,-53 7.25,-61.75 11,-65.5 15.5,-65.5 16.5,-64.5 16.5,-55.5 19.75,-52.25 34.25,-52.25 36,-52.25 36,-54.75 38.5,-57.25 38.5,-61 43,-61 47.5,-61 47.5,-54.5 49.25,-52.75
AGND2 on Bottom Layer "Top Layer-No Net" (solid, remove dead copper, pour order 1013): 70.485,-159.484 70.485,-172.184 70.358,-172.311 62.103,-172.311 61.976,-172.184 61.976,-159.484 62.23,-159.23 70.231,-159.23 70.485,-159.484
AGND1 on Bottom Layer "Top Layer-No Net" (solid, remove dead copper, pour order 1016): 70.345,-186.934 70.345,-199.634 70.218,-199.761 61.963,-199.761 61.836,-199.634 61.836,-186.934 62.09,-186.68 70.091,-186.68 70.345,-186.934
GND on S3 "Top Layer-No Net" (solid, remove dead copper, pour order 1019): -2.221,20.073 144.08,20.073 144.08,-206 -2.119,-206 -2.119,-150.31 -2.119,19.946
GND2 on S3 "GND2_L03_P1004" (solid, remove dead copper, pour order 1004): 55.5,-52.75 55.5,-41.75 33.75,-41.75 27,-48.5 11.75,-48.5 7.25,-53 7.25,-61.75 11,-65.5 15.5,-65.5 16.5,-64.5 16.5,-55.5 19.75,-52.25 34.25,-52.25 36,-52.25 36,-54.75 38.5,-57.25 38.5,-61 43,-61 47.5,-61 47.5,-54.5 49.25,-52.75
AGND2 on S3 "Top Layer-No Net" (solid, remove dead copper, pour order 1008): 70.485,-159.484 70.485,-172.184 70.358,-172.311 62.103,-172.311 61.976,-172.184 61.976,-159.484 62.23,-159.23 70.231,-159.23 70.485,-159.484
AGND1 on S3 "Top Layer-No Net" (solid, remove dead copper, pour order 1014): 70.345,-186.934 70.345,-199.634 70.218,-199.761 61.963,-199.761 61.836,-199.634 61.836,-186.934 62.09,-186.68 70.091,-186.68 70.345,-186.934
GND on G2 "Top Layer-No Net" (solid, remove dead copper, pour order 1015): -2.221,20.073 144.08,20.073 144.08,-206 -2.119,-206 -2.119,-150.31 -2.119,19.946
GND2 on G2 "GND2_L02_P1009" (solid, remove dead copper, pour order 1009): 55.5,-52.75 55.5,-41.75 33.75,-41.75 27,-48.5 11.75,-48.5 7.25,-53 7.25,-61.75 11,-65.5 15.5,-65.5 16.5,-64.5 16.5,-55.5 19.75,-52.25 34.25,-52.25 36,-52.25 36,-54.75 38.5,-57.25 38.5,-61 43,-61 47.5,-61 47.5,-54.5 49.25,-52.75
AGND2 on G2 "Top Layer-No Net" (solid, remove dead copper, pour order 1011): 70.485,-159.484 70.485,-172.184 70.358,-172.311 62.103,-172.311 61.976,-172.184 61.976,-159.484 62.23,-159.23 70.231,-159.23 70.485,-159.484
AGND1 on G2 "Top Layer-No Net" (solid, remove dead copper, pour order 1012): 70.345,-186.934 70.345,-199.634 70.218,-199.761 61.963,-199.761 61.836,-199.634 61.836,-186.934 62.09,-186.68 70.091,-186.68 70.345,-186.934
no net on Top Solder "Bottom Layer-No Net" (solid): 32.357,-163.087 32.357,-162.767 ccw(c29.817,-162.767) 29.817,-160.227 29.309,-160.227 29.309,-158.642 32.357,-158.642 33.5,-158.642 33.5,-159.912 33.5,-163.087 33.119,-163.087 32.357,-163.087
no net on Top Solder "Bottom Layer-No Net" (solid): 32.357,-177.587 32.357,-177.267 ccw(c29.817,-177.267) 29.817,-174.727 29.309,-174.727 29.309,-173.142 32.357,-173.142 33.5,-173.142 33.5,-174.412 33.5,-177.587 33.119,-177.587 32.357,-177.587
no net on Top Solder "Bottom Layer-No Net" (solid): 32.5,-193.445 32.5,-193.124 ccw(c29.96,-193.124) 29.96,-190.584 29.452,-190.584 29.452,-189 32.5,-189 33.643,-189 33.643,-190.27 33.643,-193.445 33.262,-193.445 32.5,-193.445
no net on Top Solder "Bottom Layer-No Net" (solid): 29.633,-188.244 29.954,-188.244 ccw(c29.954,-185.704) 32.494,-185.704 32.494,-185.196 34.078,-185.196 34.078,-188.244 34.078,-189.387 32.808,-189.387 29.633,-189.387 29.633,-189.006 29.633,-188.244
no net on Top Solder "Bottom Layer-No Net" (solid): 29.633,-172.494 29.954,-172.494 ccw(c29.954,-169.954) 32.494,-169.954 32.494,-169.446 34.078,-169.446 34.078,-172.494 34.078,-173.637 32.808,-173.637 29.633,-173.637 29.633,-173.256 29.633,-172.494
GND on Top Layer "Top Layer-No Net" (solid, remove dead copper, pour order 1020): -2.221,20.073 144.08,20.073 144.08,-206 -2.119,-206 -2.119,-150.31 -2.119,19.946
GND2 on Top Layer "GND2_L01_P1017" (solid, remove dead copper, pour order 1017): 55.5,-52.75 55.5,-41.75 33.75,-41.75 27,-48.5 11.75,-48.5 7.25,-53 7.25,-61.75 11,-65.5 15.5,-65.5 16.5,-64.5 16.5,-55.5 19.75,-52.25 34.25,-52.25 36,-52.25 36,-54.75 38.5,-57.25 38.5,-61 43,-61 47.5,-61 47.5,-54.5 49.25,-52.75

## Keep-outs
Keep-Out Layer:
  lines w0.254: -0.008,13.127 cw(c4.864,13.127) 4.864,18 28.448,18 cw(c28.448,14.276) 31.081,16.909 32.564,15.426 ccw(c34.646,17.508) 34.646,14.564 ccw(c34.646,17.508) 36.727,15.426 38.21,16.909 cw(c40.843,14.276) 40.843,18 ; 0,-201 ccw(c5,-201) 5,-206 ; 0,-200.981 0,13.127 ; 4.997,-206 ccw(c4.997,-202.276) 7.63,-204.909 9.113,-203.426 cw(c11.194,-205.508) 11.194,-202.564 cw(c11.194,-205.508) 13.276,-203.426 14.759,-204.909 ccw(c17.392,-202.276) 17.392,-206 133.557,-206 ccw(c133.557,-202.934) 135.725,-205.102 142.102,-198.725 ccw(c139.934,-196.557) 143,-196.557 143,-13.245 140,-13.245 140,7.583 143,7.583 143,8.697 ccw(c139.934,8.697) 142.102,10.865 135.865,17.102 ccw(c133.697,14.934) 133.697,18 40.752,18

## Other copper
Top Layer:
  region net +5.5V: 102.676,-17 102.676,-15.782 99.526,-15.782 99.526,-17
  region net +5.5V: 88.047,-17.467 88.047,-16.25 84.897,-16.25 84.897,-17.467
  region net +5.5V: 108.353,-6.25 108.353,-18 111,-18 111,-6.25
  region net +5.5V: 119.5,-8.5 119.5,-19 122,-19 122,-8.5
  region net +5.5V: 102.5,-11.75 102.5,-9.25 86,-9.25 86,-11.75
  rectangle net NetC57_1: 77.75,-11.684 82.75,13
  rectangle net OPD1: 3.464,-168.038 9.687,-167.038
  rectangle net NetC2008_1: 13.284,-167.978 20.685,-166.978
  rectangle net RPD1: 3.87,-183.177 9.788,-182.177
  rectangle net RPD2: 3.75,-198.385 9.712,-197.385
  rectangle net NetC2036_1: 12.778,-198.351 21,-197.351
  rectangle net NetC2022_1: 12.727,-183.142 20.773,-182.142
  rectangle net NetC57_1: 78.486,-11.684 84.5,-9.347
  region net +5.5V: 100.628,-11.75 100.628,-17.034 103.295,-17.034 103.295,-11.75
  region net 3.3VCC: 99.485,-18.059 99.485,-19.405 103.149,-19.405 103.149,-18.059
  region net +5.5V: 88.53,-17.467 88.53,-11.371 85.99,-11.371 85.99,-17.467
  region net 3.3VCC_1: 88.485,-19.88 88.485,-18.56 84.77,-18.56 84.77,-19.88
  region net 3.3VCC_1: 88.58,-22.141 88.58,-18.153 87.412,-18.153 87.412,-22.141
  region net 3.3VCC: 103.25,-24.75 103.25,-17.75 102,-17.75 102,-24.75
  pour cut-out: 116,-29.5 127.458,-29.5 127.458,-36 121.25,-36 121.25,-33.828 116,-33.828
  pour cut-out: 111.108,-129.65 111.108,-145.25 108.708,-145.25 108.708,-129.65
  pour cut-out: 27.764,-130.16 27.764,-113.097 22.5,-113.097 22.5,-130.16
  pour cut-out: 33.5,-115.25 33.5,-102.5 29.187,-98.187 21.25,-98.187 21.25,-115.25
  pour cut-out: 26.75,-146.25 26.75,-131.938 20.75,-131.938 20.75,-146.25
  region net +5.5V: 102.5,-9.25 105.5,-6.25 115.25,-6.25 119.5,-6.25 122,-8.5 122,-10 119.5,-10 119.5,-9.5 118.5,-8.5 116,-8.5 107.5,-8.5 104.25,-11.75 102.5,-11.75
  pour cut-out: 37.5,-57.676 35.324,-55.5 36.75,-55.5 38.5,-57.25 38.5,-61 37.5,-61
  region net +5V: 112.2,-17.9 112.2,-25.25 113.4,-25.25 113.4,-18.6 112.7,-17.9
  region net +5V_1: 123.2,-17.75 123.2,-24.7 124,-25.5 132.75,-25.5 135.5,-28.25 137,-28.25 137,-26.25 135,-24.25 124.75,-24.25 124.25,-23.75 124.25,-18.25 123.75,-17.75
  pour cut-out: 102.945,-160.991 102.855,-160.991 102.855,-163.734 97.692,-163.734 97.692,-160.001 102.945,-160.001
  pour cut-out: 97.5,-174.25 98.037,-174.25 98.5,-174.713 98.5,-177.412 97.412,-177.412 97.25,-177.25 97.25,-174.5
  pour cut-out: 21.921,-7.492 35.45,-7.492 35.45,-10.539 28.899,-10.539 21.921,-10.539
  pour cut-out: 108.815,-125.593 108.815,-110.343 129.643,-110.343 129.643,-125.593
  pour cut-out: 24.305,-93.601 36.905,-93.601 36.905,-86.001 24.305,-86.001
  pour cut-out: 85.75,1.5 85.75,-8.5 85.36,-8.89 83.074,-8.89 82.947,-8.763 82.947,0.254 84.193,1.5
  pour cut-out: 61.861,-16.256 65.861,-16.256 65.861,-23.063 61.861,-23.063
  pour cut-out: 61.874,5.925 65.874,5.925 65.874,-0.882 61.874,-0.882
  pour cut-out: 25.894,15.562 25.894,14.469 31.222,14.469 31.222,14.122 32.144,13.2 32.458,13.515 34.965,13.515 34.976,13.504 34.976,10.507 32.177,10.507 31.424,11.261 25.535,11.261 25.375,11.421 25.375,15.043
  pour cut-out: 21.057,15.562 21.057,11.575 23.546,11.575 23.546,15.562
  pour cut-out: 107.542,-84.75 107.542,-80.25 119.25,-80.25 119.25,-84.75
  pour cut-out: 115.75,-77.043 115.75,-84.75 110.5,-84.75 110.5,-77.043
  pour cut-out: 85.392,6.25 85.392,-1 95.5,-1 95.5,6.25
  pour cut-out: 23.805,-11.895 30.028,-11.895 30.028,-11.896 30.028,-24.696 23.805,-24.696
  pour cut-out: 23.805,10.623 30.028,10.623 30.028,10.622 30.028,-2.178 23.805,-2.178
  pour cut-out: 142.75,-3.953 130.708,-3.953 128.5,-1.745 128.5,10.631 142.75,10.631
  pour cut-out: 5.928,-195.392 8.315,-195.392 8.315,-196.816 5.928,-196.816
  pour cut-out: 14.878,-195.392 17.265,-195.392 17.265,-196.816 14.878,-196.816
  pour cut-out: 14.878,-180.176 17.265,-180.176 17.265,-181.6 14.878,-181.6
  pour cut-out: 5.928,-180.176 8.315,-180.176 8.315,-181.6 5.928,-181.6
  pour cut-out: 5.928,-165.139 8.315,-165.139 8.315,-166.563 5.928,-166.563
  pour cut-out: 14.878,-165.139 17.265,-165.139 17.265,-166.563 14.878,-166.563
  region net NetC2022_2: 25.847,-182.821 25.847,-182.466 23.942,-182.466 23.257,-182.135 22.128,-182.135 22.128,-183.135 23.257,-183.135 23.968,-182.821
  region net NetC2008_2: 25.76,-167.707 25.76,-167.351 23.855,-167.351 23.169,-167.021 22.041,-167.021 22.041,-168.021 23.169,-168.021 23.88,-167.707
  region net NetC2036_2: 25.847,-198.061 25.847,-197.706 23.942,-197.706 23.257,-197.375 22.128,-197.375 22.128,-198.375 23.257,-198.375 23.968,-198.061
  pour cut-out: 23.36,-169.063 23.955,-168.468 23.955,-166.182 23.787,-166.014 0,-166.014 0,-169.063
  pour cut-out: 0,-184.201 0,-181.152 24.051,-181.152 24.978,-182.079 24.978,-182.827 23.638,-184.167 21.263,-184.167 21.228,-184.201
  pour cut-out: 0,-199.41 0,-196.23 23.65,-196.23 24.082,-196.662 24.082,-198.44 23.112,-199.41
  pour cut-out: 51.232,-61.075 43.782,-61.075 43.782,-54.425 51.232,-54.425
  region net GND2: 44.625,-58 43.625,-59 40.407,-59 40.407,-56.5 43.625,-56.5 44.625,-57.5
  region net NetD1_2: 92.858,12.825 99.858,12.825 101.783,10.9 101.783,4.5 101.608,4.325 101.358,4.325 101.183,4.5 101.183,6 99.358,7.825 94.108,7.825 92.858,7.825
  region net 24VIN: 102.507,4.25 102.507,6.175 105.955,9.622 127.878,9.622 130.5,9.622 130.5,6 128.75,4.25 126.75,4.25
  region net VIN: 133.5,8.75 138,8.75 138,-1.25 132.08,-1.25 132.08,3.83 133.5,5.25
  pour cut-out: 80,16.75 93,16.75 93,3.75 80,3.75
  pour cut-out: 79.987,16.787 92.987,16.787 92.987,3.787 79.987,3.787
S3:
  pour cut-out: 108.815,-125.593 108.815,-110.343 129.643,-110.343 129.643,-125.593
  pour cut-out: 24.305,-93.601 36.905,-93.601 36.905,-86.001 24.305,-86.001
  pour cut-out: 23.805,10.685 30.028,10.685 30.028,10.684 30.028,-2.116 23.805,-2.116
  pour cut-out: 23.805,-11.895 30.028,-11.895 30.028,-11.896 30.028,-24.696 23.805,-24.696
  pour cut-out: 51.232,-61.075 43.782,-61.075 43.782,-54.425 51.232,-54.425
  pour cut-out: 80,16.787 93,16.787 93,3.787 80,3.787
G2:
  pour cut-out: 108.815,-125.593 108.815,-110.343 129.643,-110.343 129.643,-125.593
  pour cut-out: 24.305,-93.601 36.905,-93.601 36.905,-86.001 24.305,-86.001
  pour cut-out: 23.805,-11.895 30.028,-11.895 30.028,-11.896 30.028,-24.696 23.805,-24.696
  pour cut-out: 23.805,10.685 30.028,10.685 30.028,10.684 30.028,-2.116 23.805,-2.116
  pour cut-out: 51.232,-61.075 43.782,-61.075 43.782,-54.425 51.232,-54.425
  pour cut-out: 79.987,16.787 92.987,16.787 92.987,3.787 79.987,3.787
Bottom Layer:
  rectangle net 3.3VCC: 112.903,-143.129 121.285,-140.843
  rectangle net 3.3VCC: 114.173,-134.239 120.904,-131.953
  pour cut-out: 108.815,-125.593 108.815,-110.343 129.643,-110.343 129.643,-125.593
  pour cut-out: 24.305,-93.601 36.905,-93.601 36.905,-86.001 24.305,-86.001
  pour cut-out: 23.805,10.66 30.028,10.66 30.028,10.659 30.028,-2.141 23.805,-2.141
  pour cut-out: 23.805,-11.895 30.028,-11.895 30.028,-11.896 30.028,-24.696 23.805,-24.696
  pour cut-out: 51.232,-61.075 43.782,-61.075 43.782,-54.425 51.232,-54.425
  pour cut-out: 80,16.787 93,16.787 93,3.787 80,3.787

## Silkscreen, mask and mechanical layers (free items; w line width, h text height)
Top Overlay:
  circle w0.127: c143.73,-206.386 r1.8
  circle w0.127: c143.386,18.66 r1.8
  lines w0.127: 139.603,22 139.603,18.688 ccw(c143.36,18.688) 143.36,14.931 146.961,14.931 ; 140.002,-209.961 140.002,-206.36 cw(c143.758,-206.36) 143.758,-202.603 147.07,-202.603
  lines w0.254: -0.25,-190.366 29.47,-190.366 ; -0.25,-188.36 29.5,-188.36 ; -0.25,-174.548 29.485,-174.548 ; -0.25,-172.548 29.485,-172.543 ; 0.254,-160.199 29.479,-160.199 ; 29.47,-190.371 cw(c29.47,-193.371) 32.47,-193.371 ; 29.479,-160.205 cw(c29.479,-163.205) 32.479,-163.205 ; 29.485,-174.541 cw(c29.485,-177.541) 32.485,-177.541 ; 29.485,-172.548 ccw(c29.485,-169.548) 32.485,-169.548 ; 29.499,-188.362 ccw(c29.499,-185.362) 32.499,-185.362 ; 32.491,-206 32.491,-193.371 ; 32.491,-185.404 32.491,-177.541 ; 32.491,-169.557 32.491,-163.128 ; 34.491,-206 34.491,-158.192 ; 34.5,-158.191 0.254,-158.197 ; 0.254,-158.197 0.254,-158.197 ; -4,-210 -4,22 147,22 147,-210 -4,-210
  text "+24V" at 130,-1.75 h1.52 r90
  text "GND" at 130,-8.5 h1.52 r90
  text "WS7.820.438.V01" at 75.75,-50.75 h2 r90
  text "OPD" at 10.25,-164 h1.52
  text "RPD" at 10.25,-179 h1.52
  text "INPD" at 10.25,-194.5 h1.52
Top Solder:
  rectangle: 131.08,-1.25 138,3.75
  rectangle: 131.032,-9.005 138,-4.005
  region: 34.491,-166.309 34.491,-158.25 32.491,-158.25 32.491,-166.309
  rectangle: 1.744,-170.397 17.779,-169.08
  rectangle: 1.744,-185.51 17.779,-184.193
  region: 34.491,-181.295 34.491,-169.306 32.491,-169.306 32.491,-181.295
  region: 34.491,-196.179 34.491,-184.368 32.491,-184.368 32.491,-196.179
  rectangle: 1.744,-200.726 17.779,-199.41
  region: 34.491,-206 34.491,-199.608 32.491,-199.608 32.491,-206
  region: 32.741,-172.466 0.254,-172.466 0.254,-174.466 32.741,-174.466
  region: 32.572,-188.4 0.251,-188.4 0.251,-190.305 32.572,-190.305
  region: 34.5,-160.182 34.5,-158.197 0.254,-158.197 0.254,-160.182
  region: 25.847,-198.061 25.847,-197.706 23.942,-197.706 23.257,-197.375 22.128,-197.375 22.128,-198.375 23.257,-198.375 23.968,-198.061
  region: 25.847,-182.821 25.847,-182.466 23.942,-182.466 23.257,-182.135 22.128,-182.135 22.128,-183.135 23.257,-183.135 23.968,-182.821
  region: 25.76,-167.707 25.76,-167.351 23.855,-167.351 23.169,-167.021 22.041,-167.021 22.041,-168.021 23.169,-168.021 23.88,-167.707
Bottom Solder:
  rectangle: -0.435,-206.25 23.942,-158.233
  region: 77.622,18 136.047,18 141.08,12.967 144.08,10.25 144.08,7.583 141.08,7.583 141.08,-13.245 144.08,-13.245 144.08,-22.25 77.622,-22.25
  region: 47.25,0.38 47.25,5.75 44.75,8.25 44.75,11.5 57,11.5 57,3.5 51.75,3.5 51.75,0.38
  region: 47.25,-21.858 47.25,-16.489 44.75,-13.989 44.75,-10.75 57,-10.75 57,-18.739 51.75,-18.739 51.75,-21.858
Mechanical 1:
  text "LAN与CAN兼容" at -72.75,5.639 h10
  text "24V电源输入" at 169,-6.361 h10
  text "WLAN" at -35.5,-9.75 h10
  text "POWER LED (12个)" at -93.25,-36.361 h10
  text "RF_EN IO+PWMIN+信号处理板接口/5V1A供电" at 168.75,-36.982 h10
  text "2x机柜温度，1合成器温度，电源隔离485，带温度流量计，TTL UART" at -295.5,-69.574 h10
  text "一路激励插件温度+3路检流模块ADC输入" at 165,-71.861 h10
  text "三色报警灯可控电源，2个电磁阀可控电源" at 165.25,-104.361 h10
  text "LCD，漏液传感器，电源开关，2x24V机身安全联锁输入，24V联锁输出" at -296.461,-105.824 h10
  text "power LED 6个,5V快联锁输入、24V人身安全输入、24V联锁输出" at -271.461,-137.472 h10
  text "整机状态灯信号+复位IO" at 163.5,-139.074 h10
  text "主控编程口" at 163.75,-165.861 h10
  text "正向检波" at -50.491,-170.861 h10
  text "ADC-MCU编程口" at 163.516,-183.882 h10
  text "反向检波" at -51.491,-186.111 h10
  text "输入检波" at -51.257,-201.475 h10
Drill Drawing:
  text "'.Legend'" at 70.786,-124.25 h1.52 r270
